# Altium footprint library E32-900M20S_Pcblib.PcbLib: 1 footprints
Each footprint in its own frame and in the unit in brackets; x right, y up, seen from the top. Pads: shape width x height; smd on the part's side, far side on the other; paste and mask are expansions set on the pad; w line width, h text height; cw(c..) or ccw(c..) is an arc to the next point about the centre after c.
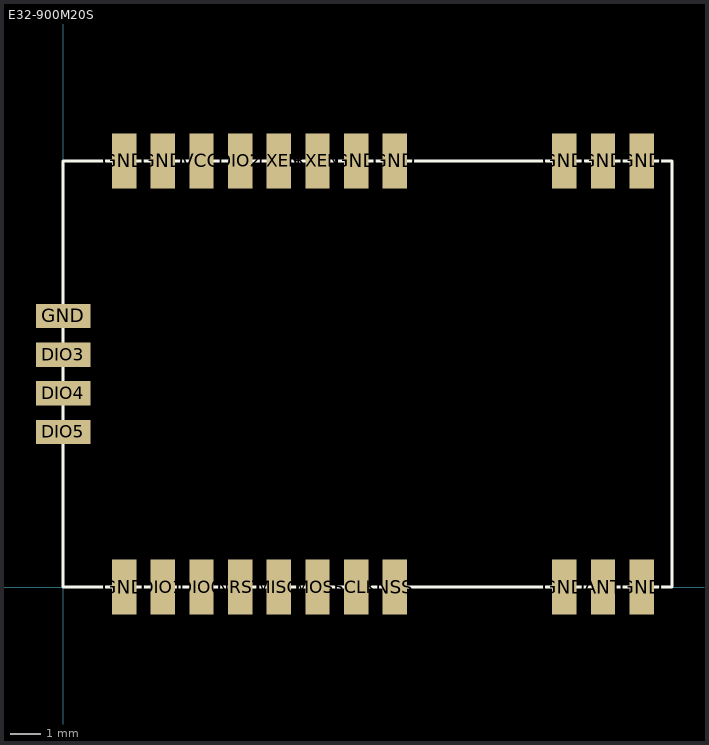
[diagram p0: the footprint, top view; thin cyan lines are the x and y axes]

## E32-900M20S [mm]
pads (26):
  rect 0.8x1.8 smd: ANT(17.73,0) DIO0(4.54,0) DIO1(3.27,0) DIO2(5.81,14) GND(2,0) GND(2,14) GND(3.27,14) GND(9.62,14) GND(10.89,14) GND(16.46,0) GND(16.46,14) GND(17.73,14) GND(19,0) GND(19,14) MISO(7.08,0) MOSI(8.35,0) NRST(5.81,0) NSS(10.89,0) RXEN(8.35,14) SCLK(9.62,0) TXEN(7.08,14) VCC(4.54,14)
  rect 1.8x0.8 smd: DIO3(0,7.636) DIO4(0,6.366) DIO5(0,5.096) GND(0,8.906)
Top Overlay:
  lines w0.1: 0,0 0,14 20,14 20,0 0,0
